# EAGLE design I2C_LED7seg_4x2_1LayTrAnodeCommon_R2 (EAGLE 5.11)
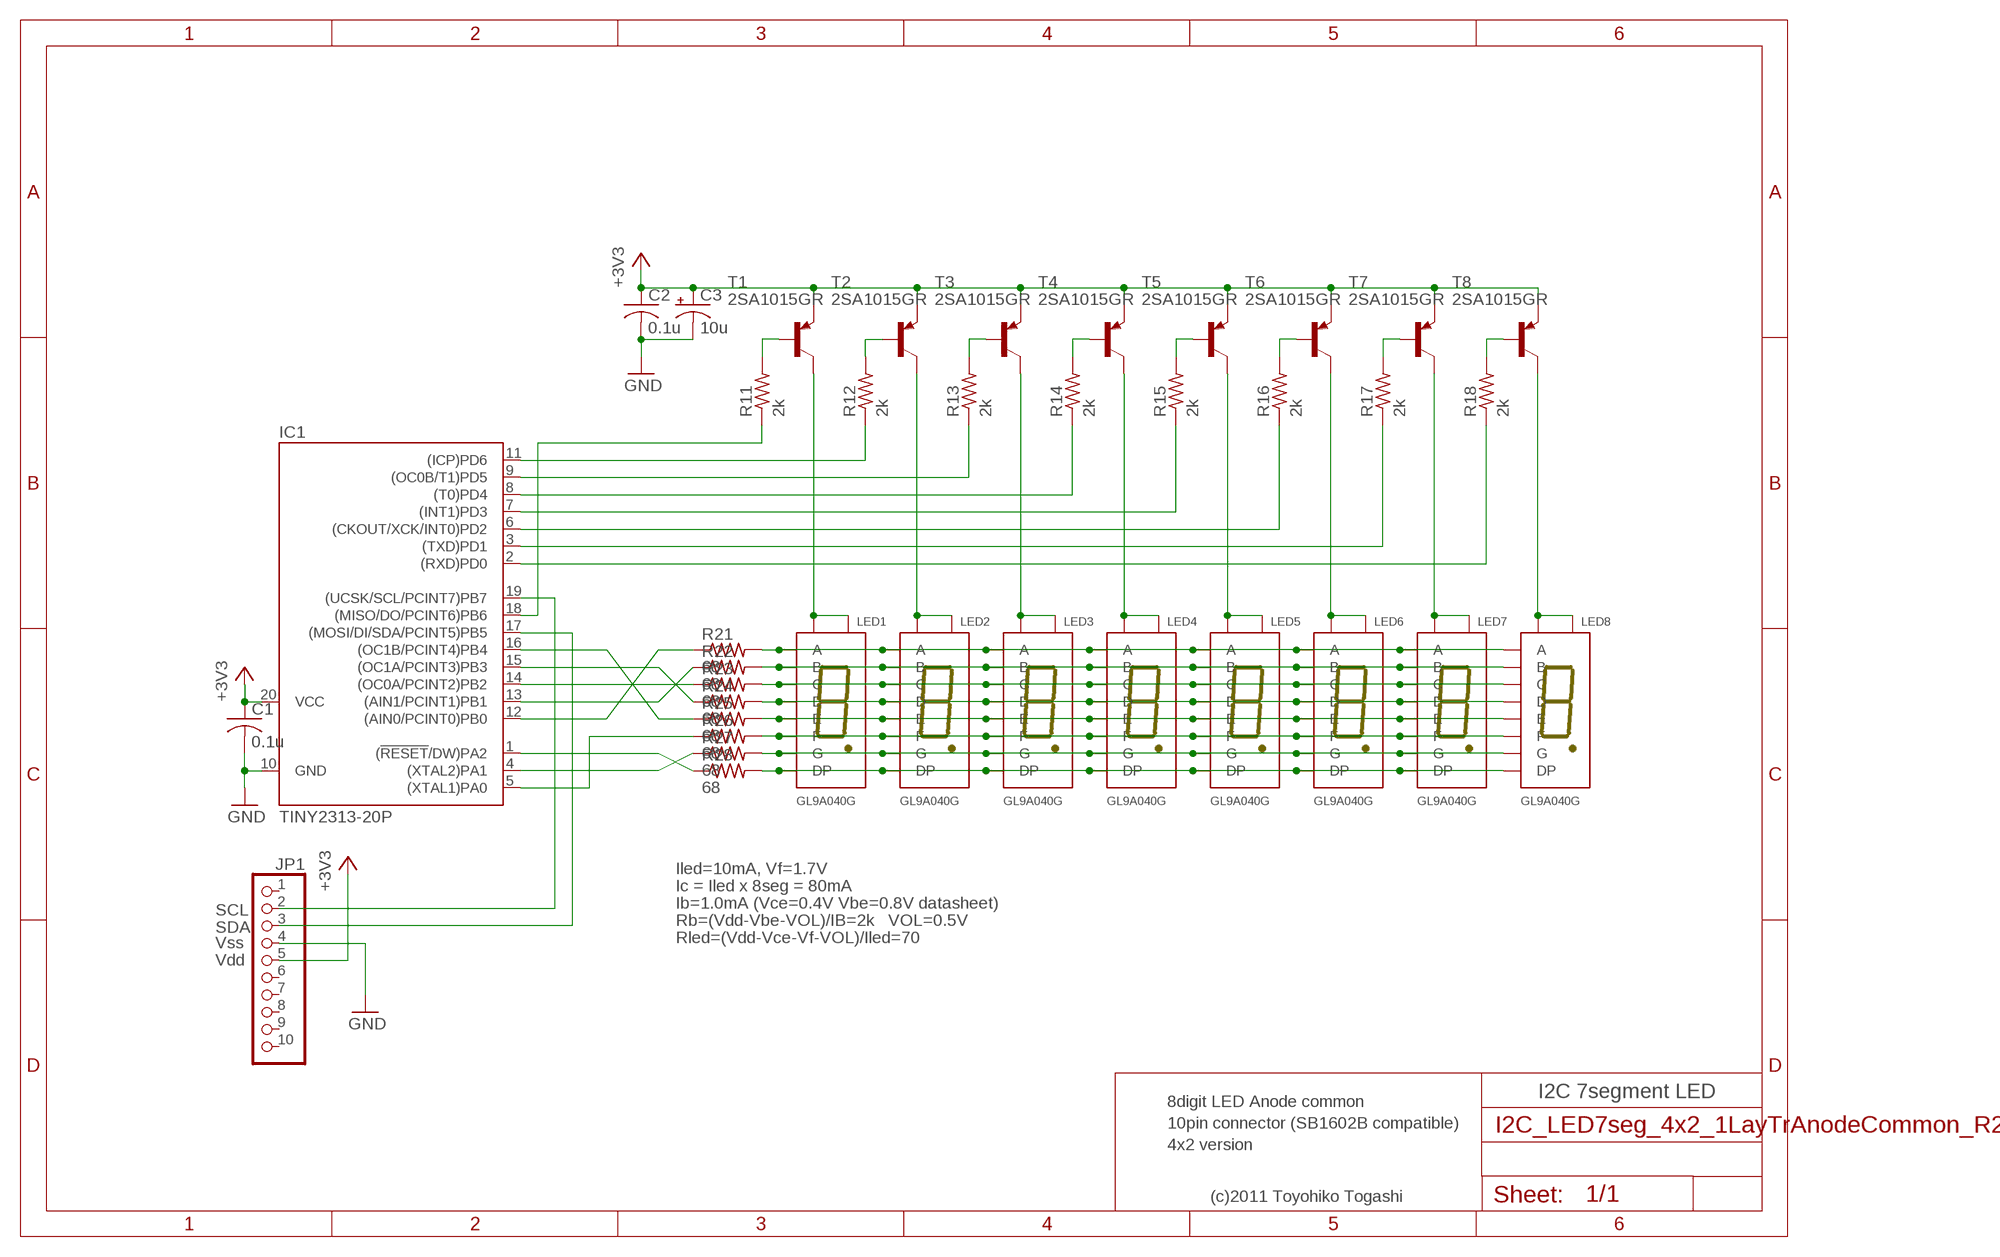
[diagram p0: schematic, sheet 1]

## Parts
C1  0.1u  C-US025-024X044  [C025-024X044]
C2  0.1u  C-US025-024X044  [C025-024X044]
C3  10u  CPOL-USE2.5-6  [E2,5-6]
IC1  TINY2313-20P  [DIL20]
JP1  PINHD-1X10  [1X10]
LED1  GL9A040G  [GL9A040G]
LED2  GL9A040G  [GL9A040G]
LED3  GL9A040G  [GL9A040G]
LED4  GL9A040G  [GL9A040G]
LED5  GL9A040G  [GL9A040G]
LED6  GL9A040G  [GL9A040G]
LED7  GL9A040G  [GL9A040G]
LED8  GL9A040G  [GL9A040G]
R11  2k  R-US_0204/5  [0204/5]
R12  2k  R-US_0204/5  [0204/5]
R13  2k  R-US_0204/5  [0204/5]
R14  2k  R-US_0204/5  [0204/5]
R15  2k  R-US_0204/5  [0204/5]
R16  2k  R-US_0204/5  [0204/5]
R17  2k  R-US_0204/5  [0204/5]
R18  2k  R-US_0204/5  [0204/5]
R21  68  R-US_0204/2V  [0204V]
R22  68  R-US_0204/2V  [0204V]
R23  68  R-US_0204/2V  [0204V]
R24  68  R-US_0204/2V  [0204V]
R25  68  R-US_0204/2V  [0204V]
R26  68  R-US_0204/7  [0204/7]
R27  68  R-US_0204/7  [0204/7]
R28  68  R-US_0204/7  [0204/7]
T1  2SA1015GR  2SC1815-PNP-TO92-BCE  [TO92-BCE]
T2  2SA1015GR  2SC1815-PNP-TO92-BCE  [TO92-BCE]
T3  2SA1015GR  2SC1815-PNP-TO92-BCE  [TO92-BCE]
T4  2SA1015GR  2SC1815-PNP-TO92-BCE  [TO92-BCE]
T5  2SA1015GR  2SC1815-PNP-TO92-BCE  [TO92-BCE]
T6  2SA1015GR  2SC1815-PNP-TO92-BCE  [TO92-BCE]
T7  2SA1015GR  2SC1815-PNP-TO92-BCE  [TO92-BCE]
T8  2SA1015GR  2SC1815-PNP-TO92-BCE  [TO92-BCE]

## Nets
+3V3: C1.1 C2.1 C3.+ IC1.20(VCC) JP1.5 T1.E T2.E T3.E T4.E T5.E T6.E T7.E T8.E
GND: C1.2 C2.2 C3.- IC1.10(GND) JP1.4
N$1: LED1.P$3(G) LED2.P$3(G) LED3.P$3(G) LED4.P$3(G) LED5.P$3(G) LED6.P$3(G) LED7.P$3(G) LED8.P$3(G) R27.2
N$2: LED1.P$7(DP) LED2.P$7(DP) LED3.P$7(DP) LED4.P$7(DP) LED5.P$7(DP) LED6.P$7(DP) LED7.P$7(DP) LED8.P$7(DP) R28.2
N$3: IC1.19((UCSK/SCL/PCINT7)PB7) JP1.2
N$4: IC1.17((MOSI/DI/SDA/PCINT5)PB5) JP1.3
N$5: LED1.P$10(A) LED2.P$10(A) LED3.P$10(A) LED4.P$10(A) LED5.P$10(A) LED6.P$10(A) LED7.P$10(A) LED8.P$10(A) R21.2
N$7: LED1.P$8(C) LED2.P$8(C) LED3.P$8(C) LED4.P$8(C) LED5.P$8(C) LED6.P$8(C) LED7.P$8(C) LED8.P$8(C) R23.2
N$8: LED1.P$5(D) LED2.P$5(D) LED3.P$5(D) LED4.P$5(D) LED5.P$5(D) LED6.P$5(D) LED7.P$5(D) LED8.P$5(D) R24.2
N$11: LED8.P$1(CA1) LED8.P$6(CA6) T8.C
N$12: LED7.P$1(CA1) LED7.P$6(CA6) T7.C
N$13: R11.2 T1.B
N$14: IC1.5((XTAL1)PA0) R26.1
N$15: IC1.4((XTAL2)PA1) R27.1
N$16: IC1.1((!RESET!/DW)PA2) R28.1
N$17: IC1.12((AIN0/PCINT0)PB0) R21.1
N$19: IC1.13((AIN1/PCINT1)PB1) R22.1
N$20: IC1.14((OC0A/PCINT2)PB2) R23.1
N$21: IC1.15((OC1A/PCINT3)PB3) R24.1
N$22: IC1.16((OC1B/PCINT4)PB4) R25.1
N$23: LED2.P$1(CA1) LED2.P$6(CA6) T2.C
N$25: IC1.18((MISO/DO/PCINT6)PB6) R11.1
N$26: R18.2 T8.B
N$27: LED4.P$1(CA1) LED4.P$6(CA6) T4.C
N$28: IC1.2((RXD)PD0) R18.1
N$30: LED6.P$1(CA1) LED6.P$6(CA6) T6.C
N$34: LED5.P$1(CA1) LED5.P$6(CA6) T5.C
N$35: R12.2 T2.B
N$37: LED3.P$1(CA1) LED3.P$6(CA6) T3.C
N$39: LED1.P$1(CA1) LED1.P$6(CA6) T1.C
N$41: LED1.P$9(B) LED2.P$9(B) LED3.P$9(B) LED4.P$9(B) LED5.P$9(B) LED6.P$9(B) LED7.P$9(B) LED8.P$9(B) R22.2
N$44: LED1.P$4(E) LED2.P$4(E) LED3.P$4(E) LED4.P$4(E) LED5.P$4(E) LED6.P$4(E) LED7.P$4(E) LED8.P$4(E) R25.2
N$45: LED1.P$2(F) LED2.P$2(F) LED3.P$2(F) LED4.P$2(F) LED5.P$2(F) LED6.P$2(F) LED7.P$2(F) LED8.P$2(F) R26.2
N$48: R13.2 T3.B
N$50: IC1.3((TXD)PD1) R17.1
N$53: IC1.7((INT1)PD3) R15.1
N$54: IC1.9((OC0B/T1)PD5) R13.1
N$60: R14.2 T4.B
N$72: R15.2 T5.B
N$84: R16.2 T6.B
N$96: R17.2 T7.B
N$98: IC1.11((ICP)PD6) R12.1
N$100: IC1.8((T0)PD4) R14.1
N$102: IC1.6((CKOUT/XCK/INT0)PD2) R16.1
Unconnected: JP1.1 JP1.6 JP1.7 JP1.8 JP1.9 JP1.10

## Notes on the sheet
- Iled=10mA, Vf=1.7V
- Ic = Iled x 8seg = 80mA
- Ib=1.0mA (Vce=0.4V Vbe=0.8V datasheet)
- SCL
- Rb=(Vdd-Vbe-VOL)/IB=2k   VOL=0.5V
- SDA
- Rled=(Vdd-Vce-Vf-VOL)/Iled=70
- Vss
- Vdd
- I2C 7segment LED
- 8digit LED Anode common
- 10pin connector (SB1602B compatible)
- 4x2 version
- (c)2011 Toyohiko Togashi

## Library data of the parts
C1 C2 = rcl:C-US: CAPACITOR, American symbol
C3 = rcl:CPOL-US: POLARIZED CAPACITOR, American symbol
IC1 = TOG:TINY2313: 8-bit AVR Microcontroller with 2K Bytes Flash Source: http://www.atmel.com .. doc2543.pdf
JP1 = pinhead:PINHD-1X10: PIN HEADER
LED1-LED8 = TOG:GL9A040G: 7 Segment LED
R11-R18 R21-R28 = rcl:R-US_: RESISTOR, American symbol
T1-T8 = transistor:*-PNP-: PNP Transistror

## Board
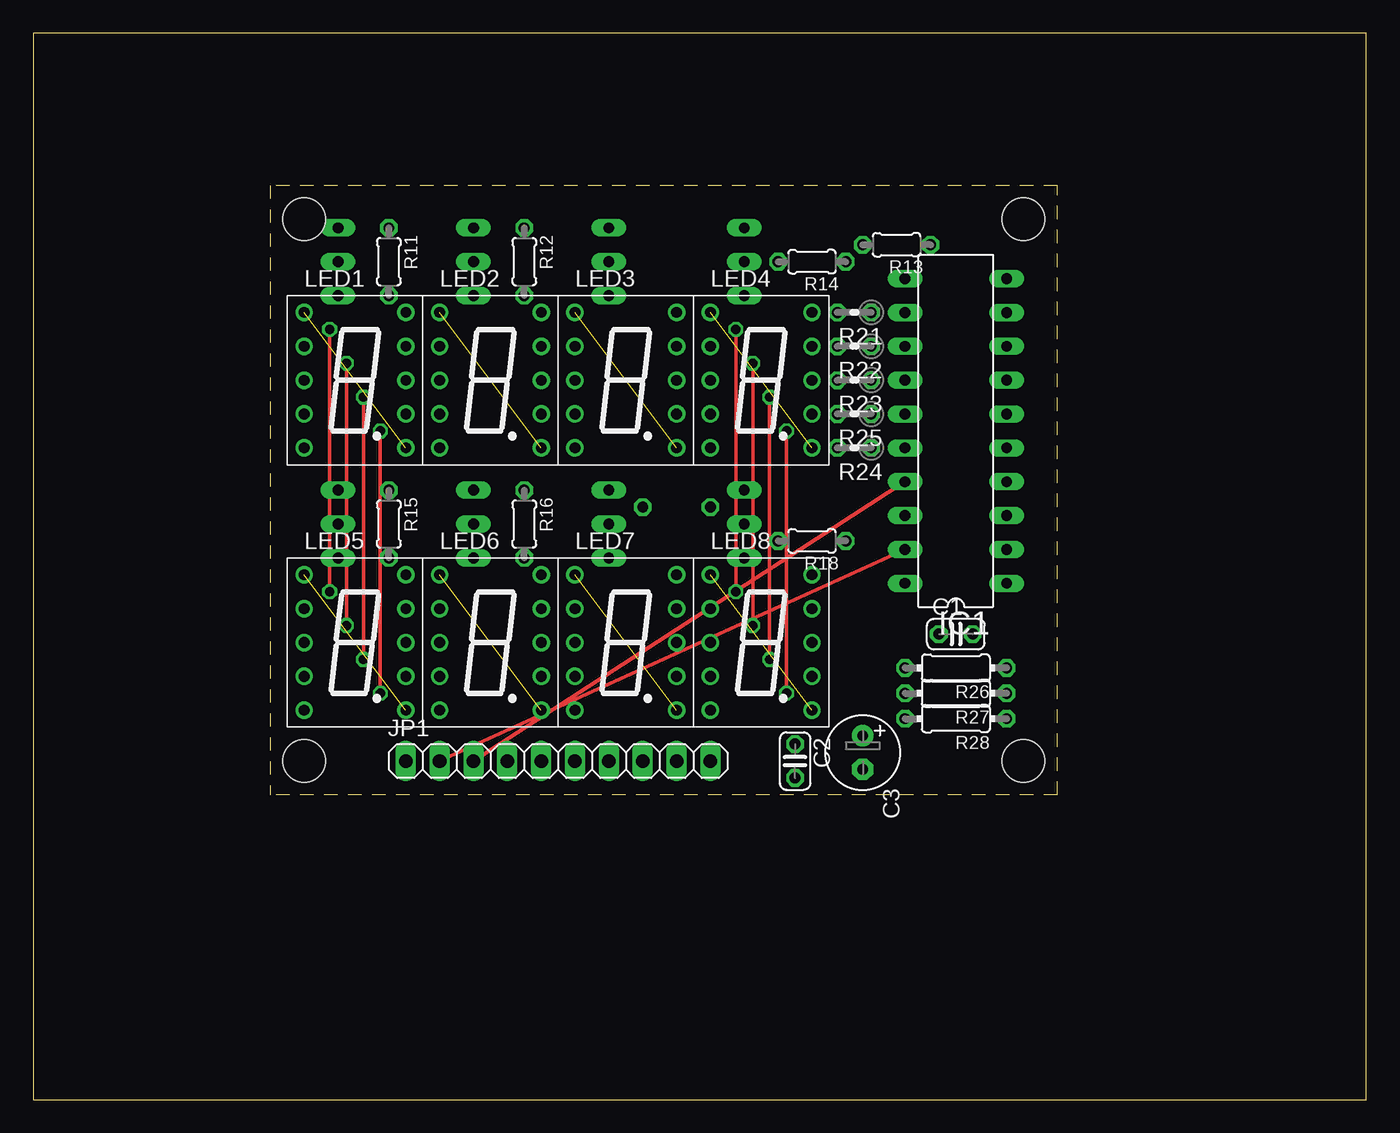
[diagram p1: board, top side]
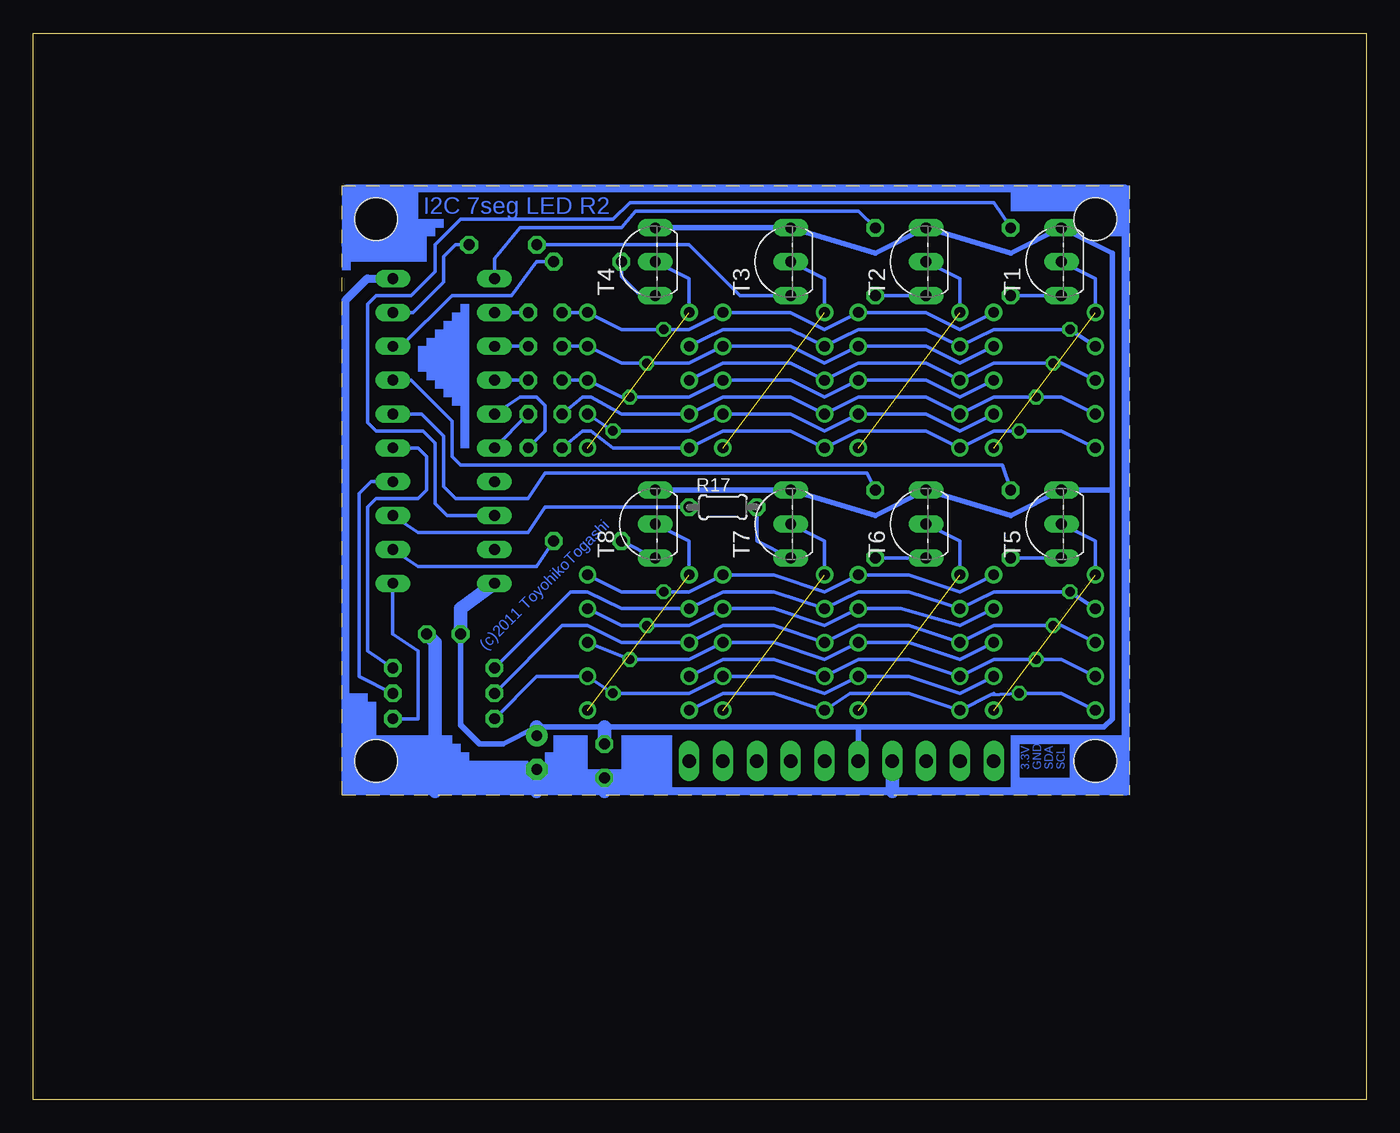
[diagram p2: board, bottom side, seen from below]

Size 100 x 80 mm. Coordinates in mm from the lower left corner, seen from the top.
Outline: 0,0 100,0 100,80 0,80 0,0
Outline: 17.78,68.58 17.78,22.86 76.83,22.86 76.83,68.58 17.78,68.58
Copper layers (1*16): Top 0.035mm / dielectric 1.5mm / Bottom 0.035mm
Design rules "default": minimum track width 10mil, minimum drill 24mil, track to track 8mil, track to pad 8mil, pad to pad 8mil, via to via 8mil, smd to smd 8mil, copper to edge 40mil, drill to drill 8mil, minimum pad ring 10mil, minimum via ring 8mil, stop-mask expansion 4mil, vias tented up to drill 0mil, thermal gap 10mil
Holes 3.2 mm at 20.32,66.04 74.3,66.04 74.3,25.4 20.32,25.4

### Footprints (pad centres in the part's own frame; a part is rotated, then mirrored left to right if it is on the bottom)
C025-024X044 = drill 0.813 octagon: 1 -1.27,0; 2 1.27,0
E2,5-6 = drill 0.813 pad 1.6 round: + -1.27,0 | drill 0.813 pad 1.6 octagon: - 1.27,0
DIL20@1 = drill 0.813 long: 1 -11.43,-3.81; 2 -8.89,-3.81; 3 -6.35,-3.81; 4 -3.81,-3.81; 5 -1.27,-3.81; 6 1.27,-3.81; 7 3.81,-3.81; 8 6.35,-3.81; 9 8.89,-3.81; 10 11.43,-3.81; 11 11.43,3.81; 12 8.89,3.81; 13 6.35,3.81; 14 3.81,3.81; 15 1.27,3.81; 16 -1.27,3.81; 17 -3.81,3.81; 18 -6.35,3.81; 19 -8.89,3.81; 20 -11.43,3.81
1X10 = drill 1.016 long: 1 -11.43,0; 2 -8.89,0; 3 -6.35,0; 4 -3.81,0; 5 -1.27,0; 6 1.27,0; 7 3.81,0; 8 6.35,0; 9 8.89,0; 10 11.43,0
GL9A040G = drill 0.8 round: P$1 -3.81,5.08; P$2 -3.81,2.54; P$3 -3.81,0; P$4 -3.81,-2.54; P$5 -3.81,-5.08; P$6 3.81,-5.08; P$7 3.81,-2.54; P$8 3.81,0; P$9 3.81,2.54; P$10 3.81,5.08
0204/5 = drill 0.813 octagon: 1 -2.54,0; 2 2.54,0
0204V = drill 0.813 octagon: 1 -1.27,0; 2 1.27,0
0204/7 = drill 0.813 octagon: 1 -3.81,0; 2 3.81,0
TO92-BCE = drill 0.813 long: B -2.54,0; C 0,0; E 2.54,0

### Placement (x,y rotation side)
C1  69.22,34.92 0 top
C2  57.15,25.4 270 top
C3  62.23,26.04 270 top
IC1  TINY2313-20P  [DIL20@1]  69.22,50.16 90 top
JP1  39.37,25.4 0 top
LED1  24.13,53.98 0 top
LED2  34.29,53.98 0 top
LED3  44.45,53.98 0 top
LED4  54.61,53.98 0 top
LED5  24.13,34.29 0 top
LED6  34.29,34.29 0 top
LED7  44.45,34.29 0 top
LED8  54.61,34.29 0 top
R11  26.67,62.87 270 top
R12  36.83,62.87 270 top
R13  64.77,64.14 180 top
R14  58.42,62.87 180 top
R15  26.67,43.18 270 top
R16  36.83,43.18 270 top
R17  48.26,44.45 0 bottom
R18  58.42,41.91 180 top
R21  61.59,59.05 180 top
R22  61.59,56.52 180 top
R23  61.59,53.98 180 top
R24  61.59,48.9 180 top
R25  61.59,51.44 180 top
R26  69.22,32.38 180 top
R27  69.22,30.48 180 top
R28  69.22,28.57 180 top
T1  22.86,62.87 90 bottom
T2  33.02,62.87 90 bottom
T3  43.18,62.87 90 bottom
T4  53.34,62.87 90 bottom
T5  22.86,43.18 90 bottom
T6  33.02,43.18 90 bottom
T7  43.18,43.18 90 bottom
T8  53.34,43.18 90 bottom

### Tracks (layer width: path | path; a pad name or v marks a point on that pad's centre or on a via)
+3V3
  Bottom 0.406: 38.1,27.94 57.15,27.94 62.23,27.94 64.77,26.67 66.53,26.67 67.94,28.09 C1.1 | 38.1,27.94 JP1.5 | 38.1,27.94 19.68,27.94 19.05,28.57 19.05,45.72 | 19.05,45.72 19.05,63.5 T1.E 26.67,63.5 T2.E 36.83,63.5 T3.E T4.E | 19.05,45.72 T5.E 26.67,43.81 T6.E 36.83,43.81 T7.E T8.E
  Bottom 1.016: IC1.20 67.94,36.83 C1.1 | 62.23,27.94 C3.+ | 57.15,27.94 C2.1
GND
  Bottom 0.61: IC1.10 74.95,61.59 76.58,59.97 76.58,23.11 69.85,23.11 62.23,23.11 57.15,23.11 35.56,23.11 18.03,23.11 18.03,68.33 76.58,68.33 76.58,64.14
  Bottom 1.016: 35.56,23.11 JP1.4 | C1.2 69.85,34.29 69.85,23.11 | 62.23,23.11 C3.- | 57.15,23.11 C2.2
N$1  (via drill 0.7)
  Top 0.254: v23.5,35.56 v23.5,55.24
  Bottom 0.254: LED4.P$3 48.26,55.24 43.18,55.24 LED3.P$3 38.1,55.24 33.02,55.24 LED2.P$3 27.94,55.24 v23.5,55.24 22.86,55.24 LED1.P$3 | LED5.P$3 22.86,35.56 v23.5,35.56 27.94,35.56 LED6.P$3 34.29,35.56 38.1,35.56 LED7.P$3 44.45,35.56 48.26,35.56 LED8.P$3 55.88,34.29 58.42,35.56 60.33,35.56 R27.2
N$2  (via drill 0.7)
  Top 0.254: v56.52,30.48 v56.52,50.16
  Bottom 0.254: LED5.P$7 30.48,30.48 34.29,31.75 LED6.P$7 40.64,30.48 44.45,31.75 LED7.P$7 50.8,30.48 v56.52,30.48 LED8.P$7 62.23,31.75 R28.2 | LED1.P$7 30.48,50.16 33.02,51.44 LED2.P$7 40.64,50.16 43.18,51.44 LED3.P$7 50.8,50.16 v56.52,50.16 LED4.P$7
N$3
  Top 0.254: JP1.2 IC1.19
N$4
  Top 0.254: JP1.3 IC1.17
N$5  (via drill 0.7)
  Top 0.254: v52.7,38.1 v52.7,57.78
  Bottom 0.254: LED1.P$10 30.48,57.78 33.02,59.05 LED2.P$10 40.64,57.78 43.18,59.05 LED3.P$10 50.8,57.78 v52.7,57.78 55.88,57.78 LED4.P$10 R21.2 | LED5.P$10 30.48,38.1 34.29,39.37 LED6.P$10 40.64,38.1 44.45,39.37 LED7.P$10 50.8,38.1 v52.7,38.1 55.88,38.1 LED8.P$10
N$7  (via drill 0.7)
  Top 0.254: v55.24,33.02 v55.24,52.7
  Bottom 0.254: LED5.P$8 30.48,33.02 34.29,34.29 LED6.P$8 40.64,33.02 44.45,34.29 LED7.P$8 50.8,33.02 v55.24,33.02 LED8.P$8 | LED1.P$8 30.48,52.7 33.02,53.98 LED2.P$8 40.64,52.7 43.18,53.98 LED3.P$8 50.8,52.7 v55.24,52.7 55.88,52.7 LED4.P$8 R23.2
N$8  (via drill 0.7)
  Top 0.254: v26.04,30.48 v26.04,50.16
  Bottom 0.254: LED8.P$5 48.26,30.48 44.45,30.48 LED7.P$5 38.73,30.48 34.29,30.48 LED6.P$5 28.19,30.35 | 28.19,30.35 27.94,30.48 | LED1.P$5 22.86,50.16 v26.04,50.16 27.94,50.16 LED2.P$5 33.02,50.16 38.1,50.16 LED3.P$5 43.18,50.16 48.26,50.16 LED4.P$5 56.52,48.9 58.17,50.16 58.8,50.16 R24.2 | 28.19,30.35 v26.04,30.48 22.86,30.48 LED5.P$5
N$11  (1 unrouted)
  Bottom 0.254: LED8.P$1 50.8,41.91 T8.C
N$12  (1 unrouted)
  Bottom 0.254: LED7.P$1 40.64,41.91 T7.C
N$13
  Bottom 0.254: T1.B R11.2
N$14
  Bottom 0.254: R26.1 74.93,33.66 74.93,44.45 74.3,45.09 71.12,45.09 70.48,45.72 70.48,48.26 71.12,48.9 IC1.5
N$15
  Bottom 0.254: R27.1 75.56,31.75 75.56,45.46 74.67,46.35 IC1.4
N$16
  Bottom 0.254: R28.1 71.12,28.57 71.12,33.66 73.03,34.92 IC1.1
N$17
  Bottom 0.254: R21.1 IC1.12
N$19
  Bottom 0.254: R22.1 IC1.13
N$20
  Bottom 0.254: R23.1 IC1.14
N$21
  Bottom 0.254: R24.1 61.59,50.16 61.59,52.07 62.23,52.7 63.5,52.7 IC1.15
N$22
  Bottom 0.254: R25.1 IC1.16
N$23  (1 unrouted)
  Bottom 0.254: LED2.P$1 30.48,61.59 T2.C
N$25
  Bottom 0.254: IC1.18 68.95,43.81 69.85,44.71 69.85,49.27 70.75,50.16 74.3,50.16 74.93,50.8 74.93,59.69 74.3,60.33 71.65,60.33 69.85,62.12 69.85,64.14 67.94,66.04 56.52,66.04 55.24,67.31 27.94,67.31 R11.1
N$26
  Bottom 0.254: T8.B R18.2
N$27  (1 unrouted)
  Bottom 0.254: LED4.P$1 50.8,61.59 T4.C
N$28
  Bottom 0.254: R18.1 62.23,40.01 71.12,40.01 IC1.2
N$30  (1 unrouted)
  Bottom 0.254: LED6.P$1 30.48,41.91 T6.C
N$34  (1 unrouted)
  Bottom 0.254: LED5.P$1 20.32,41.91 T5.C
N$35
  Bottom 0.254: T2.B R12.2
N$37  (1 unrouted)
  Bottom 0.254: LED3.P$1 40.64,61.59 T3.C
N$39  (1 unrouted)
  Bottom 0.254: LED1.P$1 20.32,61.59 T1.C
N$41  (via drill 0.7)
  Top 0.254: v53.98,35.56 v53.98,55.24
  Bottom 0.254: LED5.P$9 30.48,35.56 34.92,36.83 LED6.P$9 40.64,35.56 44.45,36.83 LED7.P$9 50.8,35.56 v53.98,35.56 55.88,35.56 LED8.P$9 | LED1.P$9 30.48,55.24 33.02,56.52 LED2.P$9 40.64,55.24 43.18,56.52 LED3.P$9 50.8,55.24 v53.98,55.24 55.88,55.24 LED4.P$9 R22.2
N$44  (via drill 0.7)
  Top 0.254: v24.77,33.02 v24.77,52.7
  Bottom 0.254: LED8.P$4 48.26,33.02 44.45,33.02 LED7.P$4 38.1,33.02 34.29,33.02 LED6.P$4 27.94,33.02 v24.77,33.02 22.86,33.02 LED5.P$4 | LED1.P$4 22.86,52.7 v24.77,52.7 27.94,52.7 LED2.P$4 33.02,52.7 38.1,52.7 LED3.P$4 43.18,52.7 48.26,52.7 LED4.P$4 55.88,51.44 58.17,52.7 58.8,52.7 R25.2
N$45  (via drill 0.7)
  Top 0.254: v22.23,38.1 v22.23,57.78
  Bottom 0.254: LED4.P$2 48.26,57.78 43.18,57.78 LED3.P$2 38.1,57.78 33.02,57.78 LED2.P$2 27.94,57.78 v22.23,57.78 LED1.P$2 | LED5.P$2 v22.23,38.1 27.94,38.1 LED6.P$2 34.29,38.1 38.1,38.1 LED7.P$2 44.45,38.1 48.26,38.1 LED8.P$2 55.88,36.83 58.42,38.1 59.69,38.1 R26.2
N$48
  Bottom 0.254: T3.B 46.99,60.33 50.8,64.14 R13.2
N$50
  Bottom 0.254: IC1.3 71.12,42.55 62.87,42.55 61.59,44.45 R17.1
N$53
  Bottom 0.254: IC1.7 71.65,53.98 68.58,50.91 68.58,48.26 67.94,47.62 27.3,47.62 R15.1
N$54
  Bottom 0.254: R13.1 68.32,64.14 69.22,63.24 69.22,61.34 71.5,59.05 IC1.9
N$60
  Bottom 0.254: T4.B 54.46,60.33 55.88,61.74 R14.2
N$72
  Bottom 0.254: T5.B R15.2
N$84
  Bottom 0.254: T6.B R16.2
N$96
  Bottom 0.254: T7.B 45.72,41.91 R17.2
N$98
  Bottom 0.254: R12.1 38.1,66.67 54.83,66.67 55.88,65.41 63.5,65.41 65.41,63.08 IC1.11
N$100
  Bottom 0.254: IC1.8 72.39,56.52 68.58,60.33 64.14,60.33 62.23,62.87 R14.1
N$102
  Bottom 0.254: IC1.6 70.87,51.44 69.22,49.78 69.22,45.98 68.32,45.09 62.87,45.09 61.59,46.99 37.47,46.99 R16.1
(copper drawn outside any net)
  shapes: Bottom area x33

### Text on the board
Bottom: I2C 7seg LED R2 | (c)2011 ToyohikoTogashi | SCL | SDA | GND | 3.3V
